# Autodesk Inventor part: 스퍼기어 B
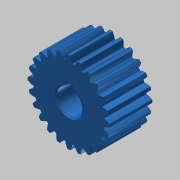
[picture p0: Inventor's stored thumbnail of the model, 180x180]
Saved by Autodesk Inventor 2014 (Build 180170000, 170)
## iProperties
Created: 2020-04
Part Number: 스퍼기어 B
Material: Steel
Document SubType Name: Modeling
Designer: mduedu
Categories: <?xml version="1.0" encoding="UTF-16"?> <MemberInstance><Categories><FamilyTemplate><FamilyTemplateParameter ValueType="xs:double" Id="1" ObjectReferenceKey="da
Density: 7.85 g/cm^3
Mass: 140.141 g
Surface Area: 65.0479 cm^2
Volume: 17.8523 cm^3
Appearance: 청록색
CustomPartVersion: 1
Author: mduedu
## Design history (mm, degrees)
sketch "Sketch1"
  geometry: C1 r 19.2 at (0, 0)
  constraints: 1 centre point
  dimensions: "d0" = 38.4 diameter of C1 (= da_da)
extrude "Extrusion1" new body sketch "Sketch1" distance "d1" = 20 (= da_b); taper "d2" = 0 deg
workplane "Work Plane2"
sketch "Sketch2"
  geometry: C1 r 19.2 at (0, 0) reference; C2 r 18 at (0, 0)
  constraints: 1 centre point, 1 coincident
  dimensions: "d3" = 36 diameter of C2 (= da_dw)
feature "피치 지름" sketch "Sketch2" dims "d4" = 10, "d5" = 0
workplane "Work Plane8"
workplane "Work Plane9"
feature "스퍼 기어" dims "da_b" = 20, "da_d" = 36, "da_aw" = 45, "da_da" = 38.4, "da_df" = 33.129, "da_dw" = 36, angle "da_beta" = 0 deg, "da_lefttooth" = 0, "da_righttooth" = 0
sketch "스케치3"
  geometry: L1 (-2, 5.657)-(2, 5.657); L2 (2, 5.657)-(2, 7.8); L3 (2, 7.8)-(-2, 7.8); L4 (-2, 7.8)-(-2, 5.657); A1 r 6 centre (0, 0) between (-2, 5.657) and (2, 5.657); 1 further point
  constraints: 8 end point, 2 parallel, 2 point on circle, 1 centre point, 1 coincident, 1 horizontal, 1 perpendicular
  dimensions: "d49" = 12 diameter of A1; "d51" = 4 distance of L2.end L3.end; "d52" = 13.8 dimension on A1 L3
extrude "돌출2" cut sketch "스케치3" stored distance "d53" = 10; taper "d54" = 0 deg
chamfer "모따기1" distance "d55" = 0.5; stored, may be unused: second distance "d56" = 2, angle "d57" = 45 deg
body "Solid1"
body "Srf1"
other parameters: "d16" = 45 (= da_aw), "d17" = 0, "d34" = 7.5 deg (computed from da_z), "d39" = 0, "d41" = 0, "d43" = 45 (= da_aw), "d46" = 45 (= da_aw), "d47" = 0, "d48" = 0
